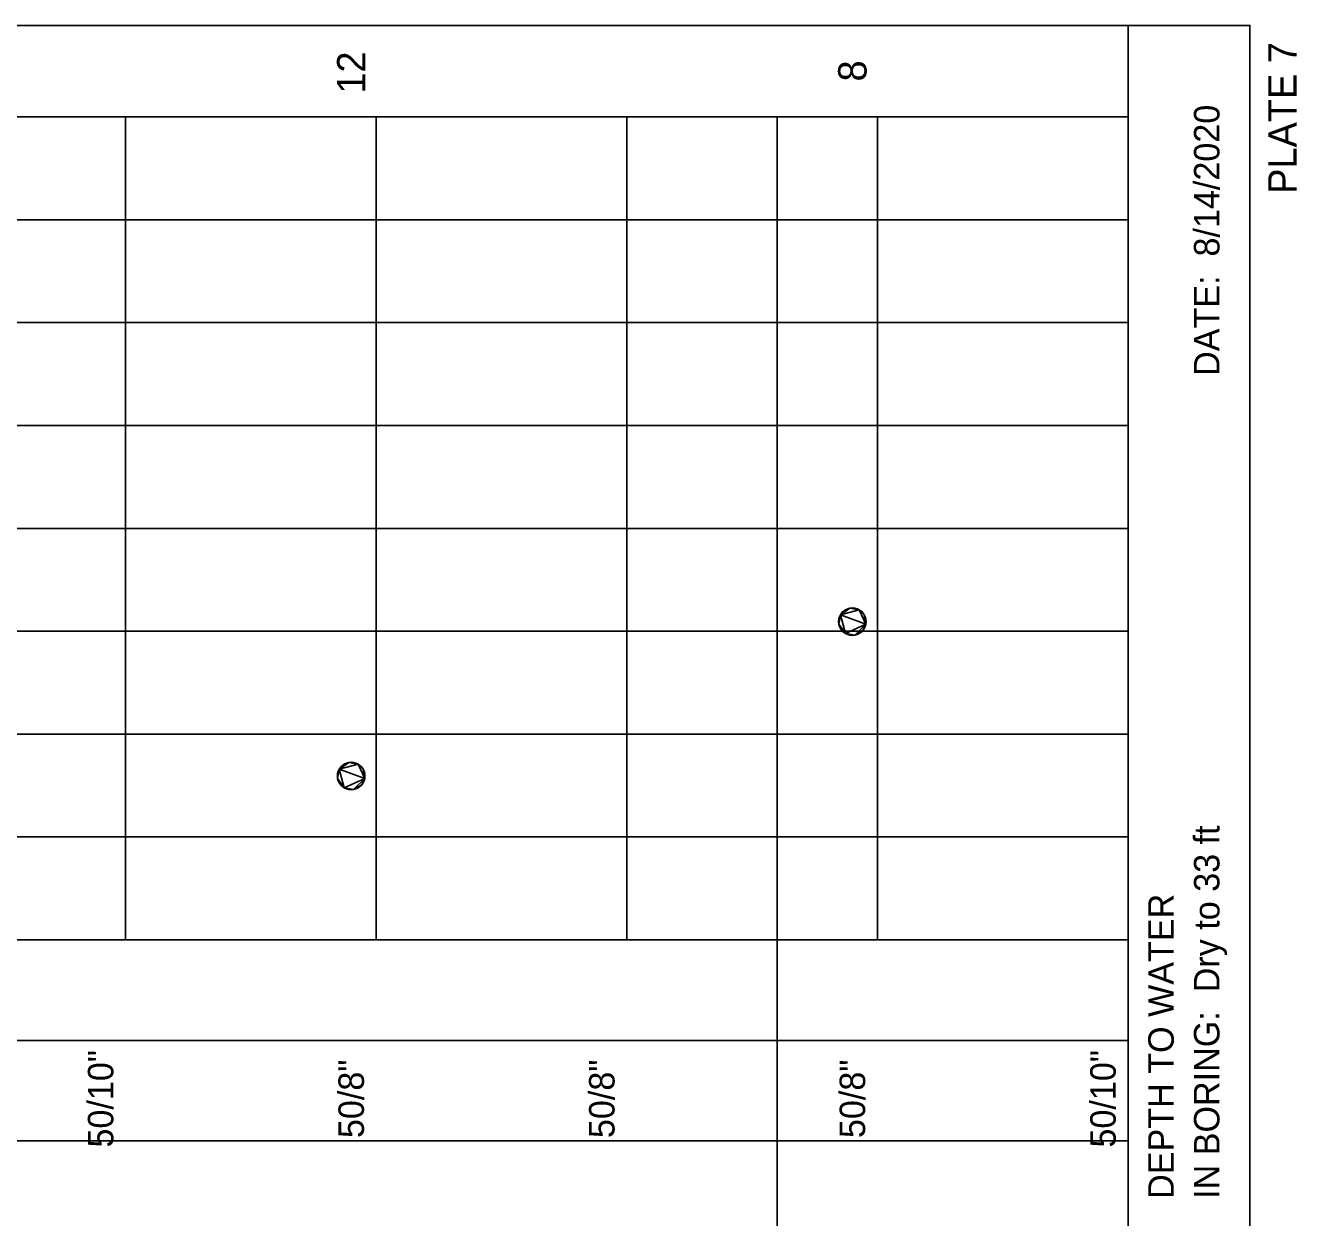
# Model space of a CAD drawing. Extents: x 1313964 to 1316843, y 2087046 to 2096619.
# Drawn here: x 1314112.29 to 1314137.66, y 2089892.52 to 2089916.31 of the extents above; entities that cross this region are included whole.
import ezdxf

# ---------------------------------------------------------------- set-up
doc = ezdxf.new("R2010")
doc.units = 0
doc.layers.add('B-Sub-Contour', color=7, linetype='Continuous')
doc.layers.add('Default', color=7, linetype='Continuous')

# ---------------------------------------------------------------- blocks, each defined once
blk = doc.blocks.new('POINT_DISPLAY')
at = {"layer": 'Default'}
blk.add_line((0, 0), (0, 0), dxfattribs=at)
blk = doc.blocks.new('DMK_101')
at = {"layer": 'Default'}
for points in [[(-3147.06, 13511.784), (-7618.476, 11878.056), (-12638.532, 6858), (-3147.06, 13511.784)], [(6097.524, 11878.056), (-3147.06, 13511.784), (-12638.532, 6858), (6097.524, 11878.056)], [(-3147.06, 13511.784), (-5451.348, 12893.04), (-7618.476, 11878.056), (-3147.06, 13511.784)], [(1626.108, 13511.784), (-760.476, 13712.952), (-3147.06, 13511.784), (1626.108, 13511.784)], [(6097.524, 11878.056), (1626.108, 13511.784), (-3147.06, 13511.784), (6097.524, 11878.056)], [(6097.524, 11878.056), (3930.396, 12893.04), (1626.108, 13511.784), (6097.524, 11878.056)], [(-14269.212, 2386.584), (-14476.476, 0), (-14269.212, -2386.584), (-14269.212, 2386.584)], [(-12638.532, 6858), (-13653.516, 4690.872), (-14269.212, 2386.584), (-12638.532, 6858)], [(-12638.532, 6858), (-14269.212, 2386.584), (-14269.212, -2386.584), (-12638.532, 6858)], [(-12638.532, 6858), (-14269.212, -2386.584), (-3147.06, -13508.736), (-12638.532, 6858)], [(-7618.476, 11878.056), (-11266.932, 8820.912), (-12638.532, 6858), (-7618.476, 11878.056)], [(-3147.06, -13508.736), (6097.524, 11878.056), (-12638.532, 6858), (-3147.06, -13508.736)], [(-7618.476, 11878.056), (-9578.34, 10506.456), (-11266.932, 8820.912), (-7618.476, 11878.056)], [(-9578.34, 10506.456), (-10456.164, 9698.736), (-11266.932, 8820.912), (-9578.34, 10506.456)], [(-3147.06, -13508.736), (11117.58, -6858), (6097.524, 11878.056), (-3147.06, -13508.736)], [(11117.58, 6858), (8060.436, 10506.456), (6097.524, 11878.056), (11117.58, 6858)], [(12751.308, 2386.584), (11117.58, 6858), (6097.524, 11878.056), (12751.308, 2386.584)], [(11117.58, -6858), (12751.308, 2386.584), (6097.524, 11878.056), (11117.58, -6858)], [(9745.98, 8820.912), (8938.26, 9698.736), (8060.436, 10506.456), (9745.98, 8820.912)], [(11117.58, 6858), (9745.98, 8820.912), (8060.436, 10506.456), (11117.58, 6858)], [(12751.308, 2386.584), (12132.564, 4690.872), (11117.58, 6858), (12751.308, 2386.584)], [(11117.58, -6858), (12751.308, -2386.584), (12751.308, 2386.584), (11117.58, -6858)], [(12751.308, -2386.584), (12952.476, 0), (12751.308, 2386.584), (12751.308, -2386.584)], [(-14269.212, -2386.584), (-13653.516, -4690.872), (-12638.532, -6858), (-14269.212, -2386.584)], [(-14269.212, -2386.584), (-12638.532, -6858), (-9578.34, -10506.456), (-14269.212, -2386.584)], [(-14269.212, -2386.584), (-9578.34, -10506.456), (-3147.06, -13508.736), (-14269.212, -2386.584)], [(-12638.532, -6858), (-11266.932, -8817.864), (-9578.34, -10506.456), (-12638.532, -6858)], [(-11266.932, -8817.864), (-10456.164, -9695.688), (-9578.34, -10506.456), (-11266.932, -8817.864)], [(-9578.34, -10506.456), (-7618.476, -11878.056), (-3147.06, -13508.736), (-9578.34, -10506.456)], [(-7618.476, -11878.056), (-5451.348, -12893.04), (-3147.06, -13508.736), (-7618.476, -11878.056)], [(-3147.06, -13508.736), (6097.524, -11878.056), (11117.58, -6858), (-3147.06, -13508.736)], [(-3147.06, -13508.736), (1626.108, -13508.736), (6097.524, -11878.056), (-3147.06, -13508.736)], [(1626.108, -13508.736), (3930.396, -12893.04), (6097.524, -11878.056), (1626.108, -13508.736)], [(6097.524, -11878.056), (8060.436, -10506.456), (11117.58, -6858), (6097.524, -11878.056)], [(8060.436, -10506.456), (9745.98, -8817.864), (11117.58, -6858), (8060.436, -10506.456)], [(8060.436, -10506.456), (8938.26, -9695.688), (9745.98, -8817.864), (8060.436, -10506.456)], [(11117.58, -6858), (12132.564, -4690.872), (12751.308, -2386.584), (11117.58, -6858)], [(-3147.06, -13508.736), (-760.476, -13716), (1626.108, -13508.736), (-3147.06, -13508.736)]]:
    blk.add_lwpolyline(points, close=True, dxfattribs=at)
blk.add_blockref('POINT_DISPLAY', (14479.524, 0), dxfattribs=at)

msp = doc.modelspace()

# ---------------------------------------------------------------- linework, layer by layer
at = {"layer": 'B-Sub-Contour'}
for points in [[(1314136.725, 2089873.434), (1314136.725, 2089916.306), (1314075.306, 2089916.306), (1314075.306, 2089873.434), (1314136.725, 2089873.434)], [(1314134.292, 2089873.434), (1314134.292, 2089916.306)], [(1314134.292, 2089914.481), (1314082.603, 2089914.481)], [(1314134.292, 2089914.481), (1314089.292, 2089914.481)], [(1314114.292, 2089898.063), (1314114.292, 2089914.481)], [(1314119.292, 2089898.063), (1314119.292, 2089914.481)], [(1314124.292, 2089898.063), (1314124.292, 2089914.481)], [(1314127.292, 2089894.049), (1314127.292, 2089914.481)], [(1314129.292, 2089898.063), (1314129.292, 2089914.481)], [(1314134.292, 2089898.063), (1314134.292, 2089914.481)], [(1314134.292, 2089912.429), (1314089.292, 2089912.429)], [(1314134.292, 2089910.377), (1314089.292, 2089910.377)], [(1314134.292, 2089908.324), (1314089.292, 2089908.324)], [(1314134.292, 2089906.272), (1314089.292, 2089906.272)], [(1314134.292, 2089904.22), (1314089.292, 2089904.22)], [(1314134.292, 2089902.167), (1314089.292, 2089902.167)], [(1314134.292, 2089900.115), (1314089.292, 2089900.115)], [(1314134.292, 2089898.063), (1314082.603, 2089898.063)], [(1314134.292, 2089898.063), (1314089.292, 2089898.063)], [(1314134.292, 2089896.056), (1314082.603, 2089896.056)], [(1314134.292, 2089894.049), (1314082.603, 2089894.049)], [(1314127.292, 2089878.178), (1314127.292, 2089894.049)]]:
    msp.add_lwpolyline(points, dxfattribs=at)

# ---------------------------------------------------------------- block references
at = {"layer": 'B-Sub-Contour', "xscale": 1.9951013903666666e-05, "yscale": 1.9951013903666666e-05, "rotation": 90}
for p in [(1314128.792, 2089904.425), (1314128.792, 2089904.425), (1314118.792, 2089901.346), (1314118.792, 2089901.346)]:
    msp.add_blockref('DMK_101', p, dxfattribs=at)

# ---------------------------------------------------------------- texts
at = {"layer": 'B-Sub-Contour'}
for s, height, p in [('PLATE 7', 0.5655, (1314137.655, 2089912.946)), ('12', 0.5655, (1314119.075, 2089914.945)), ('8', 0.566, (1314129.075, 2089915.187)), ('DATE:  8/14/2020', 0.50899, (1314136.117, 2089909.313)), ('IN BORING:  Dry to 33 ft', 0.50899, (1314136.117, 2089892.894)), ('DEPTH TO WATER', 0.50899, (1314135.205, 2089892.894)), ('50/10"', 0.509, (1314114.047, 2089893.918)), ('50/10"', 0.509, (1314134.047, 2089893.918)), ('50/8"', 0.509, (1314119.047, 2089894.107)), ('50/8"', 0.509, (1314124.047, 2089894.107)), ('50/8"', 0.509, (1314129.047, 2089894.107))]:
    msp.add_text(s, height=height, rotation=90, dxfattribs=at).set_placement(p)

doc.saveas('drawing.dxf')
